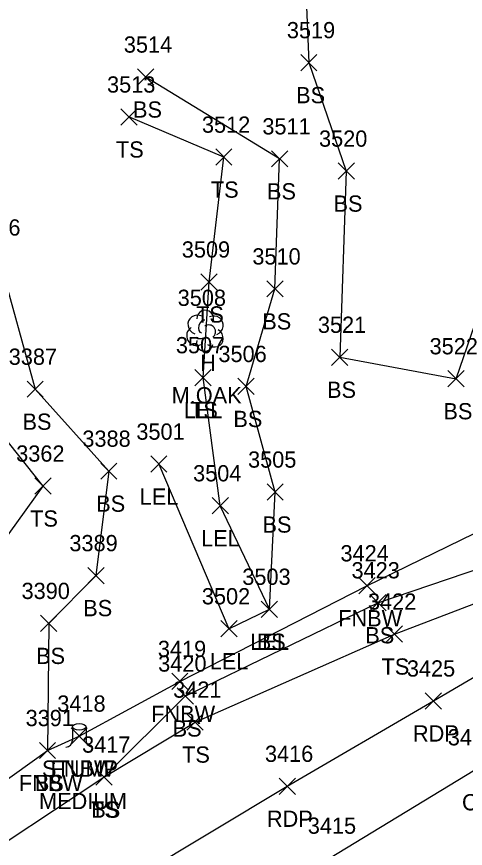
# Model space of a CAD drawing. Extents: x 1443590 to 1445966, y 578314 to 580556.
# Drawn here: x 1444037.5 to 1444092.8, y 578862 to 578964.4 of the extents above; entities that cross this region are included whole.
import ezdxf

# ---------------------------------------------------------------- set-up
doc = ezdxf.new("R2010")
doc.units = 0
for name, color, linetype in [('L_A', 7, 'Continuous'), ('L_C', 7, 'Continuous'), ('L_I', 7, 'Continuous'), ('L_TIC', 7, 'Continuous'), ('LARO', 7, 'Continuous'), ('LELB', 7, 'Continuous'), ('LFNC', 7, 'Continuous'), ('LTD', 7, 'Continuous'), ('LTS', 7, 'Continuous'), ('P_A', 7, 'Continuous'), ('P_I', 7, 'Continuous'), ('P_TIC', 7, 'Continuous'), ('PET', 7, 'Continuous'), ('PRC', 7, 'Continuous')]:
    doc.layers.add(name, color=color, linetype=linetype)

msp = doc.modelspace()

# ---------------------------------------------------------------- linework, layer by layer
at = {"layer": 'L_TIC'}
for points in [[(1444072.48, 578957.72), (1444074.48, 578959.72)], [(1444074.48, 578957.72), (1444072.48, 578959.72)], [(1444052.39, 578955.95), (1444054.39, 578957.95)], [(1444054.39, 578955.95), (1444052.39, 578957.95)], [(1444050.32, 578951.03), (1444052.32, 578953.03)], [(1444052.32, 578951.03), (1444050.32, 578953.03)], [(1444062.01, 578946.09), (1444064.01, 578948.09)], [(1444064.01, 578946.09), (1444062.01, 578948.09)], [(1444068.89, 578945.88), (1444070.89, 578947.88)], [(1444070.89, 578945.88), (1444068.89, 578947.88)], [(1444077.09, 578944.37), (1444079.09, 578946.37)], [(1444079.09, 578944.37), (1444077.09, 578946.37)], [(1444060.19, 578930.72), (1444062.19, 578932.72)], [(1444062.19, 578930.72), (1444060.19, 578932.72)], [(1444068.31, 578929.87), (1444070.31, 578931.87)], [(1444070.31, 578929.87), (1444068.31, 578931.87)], [(1444076.29, 578921.45), (1444078.29, 578923.45)], [(1444078.29, 578921.45), (1444076.29, 578923.45)], [(1444059.45, 578918.94), (1444061.45, 578920.94)], [(1444061.45, 578918.94), (1444059.45, 578920.94)], [(1444059.45, 578918.94), (1444061.45, 578920.94)], [(1444061.45, 578918.94), (1444059.45, 578920.94)], [(1444090.62, 578918.81), (1444092.62, 578920.81)], [(1444092.62, 578918.81), (1444090.62, 578920.81)], [(1444038.78, 578917.52), (1444040.78, 578919.52)], [(1444040.78, 578917.52), (1444038.78, 578919.52)], [(1444064.75, 578917.86), (1444066.75, 578919.86)], [(1444066.75, 578917.86), (1444064.75, 578919.86)], [(1444054.01, 578908.3), (1444056.01, 578910.3)], [(1444056.01, 578908.3), (1444054.01, 578910.3)], [(1444047.85, 578907.43), (1444049.85, 578909.43)], [(1444049.85, 578907.43), (1444047.85, 578909.43)], [(1444039.75, 578905.6), (1444041.75, 578907.6)], [(1444041.75, 578905.6), (1444039.75, 578907.6)], [(1444068.34, 578904.86), (1444070.34, 578906.86)], [(1444070.34, 578904.86), (1444068.34, 578906.86)], [(1444061.57, 578903.17), (1444063.57, 578905.17)], [(1444063.57, 578903.17), (1444061.57, 578905.17)], [(1444046.26, 578894.57), (1444048.26, 578896.57)], [(1444048.26, 578894.57), (1444046.26, 578896.57)], [(1444079.64, 578893.32), (1444081.64, 578895.32)], [(1444081.64, 578893.32), (1444079.64, 578895.32)], [(1444067.63, 578890.43), (1444069.63, 578892.43)], [(1444069.63, 578890.43), (1444067.63, 578892.43)], [(1444067.63, 578890.43), (1444069.63, 578892.43)], [(1444069.63, 578890.43), (1444067.63, 578892.43)], [(1444081, 578891.23), (1444083, 578893.23)], [(1444083, 578891.23), (1444081, 578893.23)], [(1444040.45, 578888.69), (1444042.45, 578890.69)], [(1444042.45, 578888.69), (1444040.45, 578890.69)], [(1444062.65, 578888.03), (1444064.65, 578890.03)], [(1444064.65, 578888.03), (1444062.65, 578890.03)], [(1444083.03, 578887.38), (1444085.03, 578889.38)], [(1444085.03, 578887.38), (1444083.03, 578889.38)], [(1444056.59, 578881.55), (1444058.59, 578883.55)], [(1444058.59, 578881.55), (1444056.59, 578883.55)], [(1444057.27, 578879.75), (1444059.27, 578881.75)], [(1444059.27, 578879.75), (1444057.27, 578881.75)], [(1444058.47, 578876.54), (1444060.47, 578878.54)], [(1444060.47, 578876.54), (1444058.47, 578878.54)], [(1444044.2, 578874.82), (1444046.2, 578876.82)], [(1444046.2, 578874.82), (1444044.2, 578876.82)], [(1444040.29, 578873.04), (1444042.29, 578875.04)], [(1444042.29, 578873.04), (1444040.29, 578875.04)], [(1444040.29, 578873.04), (1444042.29, 578875.04)], [(1444042.29, 578873.04), (1444040.29, 578875.04)], [(1444047.25, 578869.77), (1444049.25, 578871.77)], [(1444049.25, 578869.77), (1444047.25, 578871.77)], [(1444047.25, 578869.77), (1444049.25, 578871.77)], [(1444049.25, 578869.77), (1444047.25, 578871.77)]]:
    msp.add_lwpolyline(points, dxfattribs=at)
at = {"layer": 'LARO'}
msp.add_lwpolyline([(1444055.01, 578909.3), (1444063.65, 578889.03), (1444068.63, 578891.43), (1444062.57, 578904.17), (1444060.45, 578919.94)], dxfattribs=at)
at = {"layer": 'LELB'}
for points in [[(1444074.35, 578985.46), (1444072.77, 578975.47), (1444073.48, 578958.72), (1444078.09, 578945.37), (1444077.29, 578922.45), (1444091.62, 578919.81), (1444097.15, 578935.8), (1444104.08, 578947.68), (1444105.57, 578937.31), (1444105.86, 578926.31), (1444105.38, 578914.86)], [(1444028.79, 578962.23), (1444032.88, 578944.64), (1444035.34, 578934.43), (1444039.78, 578918.52), (1444048.85, 578908.43), (1444047.26, 578895.57), (1444041.45, 578889.69), (1444041.29, 578874.04)], [(1444068.63, 578891.43), (1444069.34, 578905.86), (1444065.75, 578918.86), (1444069.31, 578930.87), (1444069.89, 578946.88), (1444053.39, 578956.95)], [(1444060.45, 578919.94), (1444061.19, 578931.72), (1444063.01, 578947.09), (1444051.32, 578952.03)], [(1443938.52, 578791.48), (1443973.38, 578813.08), (1444005.23, 578834.2), (1444017.59, 578843.33), (1444019.71, 578848.08), (1444030.07, 578858.77), (1444048.25, 578870.77), (1444059.47, 578877.54), (1444084.03, 578888.38), (1444116.13, 578900.62), (1444133.65, 578911.54), (1444146.41, 578917.11), (1444149.51, 578920.45), (1444149.93, 578925.58), (1444153.52, 578930.88), (1444162.25, 578930.68), (1444174.13, 578936.01), (1444189.83, 578945.52), (1444198.3, 578950.86), (1444200.25, 578947.99), (1444203.06, 578948.48)], [(1444048.25, 578870.77), (1444058.27, 578880.75), (1444082, 578892.23), (1444114.39, 578903.2), (1444136.37, 578917.27), (1444137.43, 578920.19)], [(1443992.86, 578883.14), (1444004.82, 578882.17), (1444018.2, 578885.69), (1444031.18, 578893.34), (1444040.75, 578906.6), (1444034.4, 578914.56)]]:
    msp.add_lwpolyline(points, dxfattribs=at)
at = {"layer": 'LFNC'}
msp.add_lwpolyline([(1444008.03, 578853.09), (1444019.51, 578860.12), (1444026.6, 578863.53), (1444041.29, 578874.04), (1444045.2, 578875.82), (1444057.59, 578882.55), (1444080.64, 578894.32), (1444110.52, 578908.89), (1444116.81, 578913.3)], dxfattribs=at)
at = {"layer": 'LTD'}
msp.add_line((1444060.67, 578925.77), (1444060.67, 578925.77), dxfattribs=at)
msp.add_line((1444060.67, 578925.77), (1444060.67, 578925.77), dxfattribs=at)
msp.add_arc((1444060.72, 578927.2), 1.05, 335.5272, 180.9563, dxfattribs=at)
for centre, major_axis, ratio, start_param, end_param in [((1444059.88, 578926.43), (1.21, -0.51), 0.895232, 1.570796, 4.712389), ((1444061.71, 578926.35), (-1.14, -0.48), 0.949671, 1.570796, 4.712389), ((1444060.46, 578926.23), (-0.208, -0.792), 0.645439, 3.141593, 6.283185), ((1444061.17, 578925.6), (-0.5, 0.667), 0.989748, 3.141593, 6.283185), ((1444059.59, 578925.06), (0.58, -1.04), 0.959034, 3.141593, 6.283185), ((1444061.67, 578924.93), (-1.09, 0.79), 0.841452, 1.570796, 4.712389), ((1444060.67, 578924.27), (0.26, 1.06), 0.942809, 1.570796, 4.712389), ((1444060.21, 578925.02), (-0.625, -0.083), 0.423636, 0, 3.141593)]:
    msp.add_ellipse(centre, major_axis=major_axis, ratio=ratio, start_param=start_param, end_param=end_param, dxfattribs=at)
at = {"layer": 'LTS'}
for p, q in [((1444044.37, 578876.96), (1444044.37, 578875.29)), ((1444046.04, 578876.79), (1444046.04, 578876.96)), ((1444046.04, 578876.96), (1444046.04, 578875.29)), ((1444045.2, 578875.81), (1444045.2, 578875.81)), ((1444045.2, 578875.81), (1444045.2, 578875.81)), ((1444045.2, 578875.79), (1444045.2, 578875.79))]:
    msp.add_line(p, q, dxfattribs=at)
msp.add_circle((1444045.2, 578875.81), 0.0833, dxfattribs=at)
for centre, start, end in [((1444043.54, 578875.29), 270, 360), ((1444046.87, 578875.29), 180, 270)]:
    msp.add_arc(centre, 0.833, start, end, dxfattribs=at)
msp.add_ellipse((1444045.2, 578876.96), major_axis=(-0.833, 0), ratio=0.5, dxfattribs=at)
at = {"layer": 'P_TIC'}
for points in [[(1444087.82, 578879.14), (1444089.82, 578881.14)], [(1444089.82, 578879.14), (1444087.82, 578881.14)], [(1444069.83, 578868.64), (1444071.83, 578870.64)], [(1444071.83, 578868.64), (1444069.83, 578870.64)]]:
    msp.add_lwpolyline(points, dxfattribs=at)
at = {"layer": 'PET'}
msp.add_lwpolyline([(1443601.36, 578573.38), (1443632.23, 578593.39), (1443639.99, 578598.09), (1443685.58, 578628.02), (1443724.74, 578653.09), (1443761.98, 578676.74), (1443793.7, 578697.2), (1443832.46, 578722.27), (1443867.74, 578744.22), (1443903.66, 578767.03), (1443939.74, 578789.58), (1443974.31, 578811.25), (1444005.54, 578830.37), (1444024.78, 578842.02), (1444070.83, 578869.64), (1444088.82, 578880.14), (1444118.02, 578897.28), (1444147.48, 578914.76), (1444176.13, 578931.32), (1444203.82, 578947.29), (1444208.88, 578939.04), (1444214.07, 578930.35)], dxfattribs=at)
at = {"layer": 'PRC'}
msp.add_lwpolyline([(1443607.19, 578563.71), (1443645.74, 578588.68), (1443691.8, 578618.64), (1443730.92, 578643.94), (1443766.58, 578667.23), (1443799.08, 578688.06), (1443838.06, 578712.83), (1443872.72, 578734.91), (1443908.54, 578757.41), (1443944.72, 578780.26), (1443979.55, 578801.84), (1444011.31, 578821.61), (1444031.47, 578833.87), (1444076.05, 578860.79), (1444093.92, 578871.67), (1444123.23, 578888.92), (1444152.19, 578905.95), (1444180.96, 578922.73), (1444208.88, 578939.04)], dxfattribs=at)

# ---------------------------------------------------------------- texts
at = {"layer": 'L_A'}
for s, p in [('BS', (1444071.92, 578953.72)), ('BS', (1444051.83, 578951.95)), ('TS', (1444049.73, 578947.03)), ('TS', (1444061.42, 578942.09)), ('BS', (1444068.33, 578941.88)), ('BS', (1444076.53, 578940.37)), ('TS', (1444059.6, 578926.72)), ('BS', (1444067.75, 578925.87)), ('H', (1444060.1, 578920.77)), ('BS', (1444075.73, 578917.45)), ('LEL', (1444058.08, 578914.94)), ('TS', (1444058.86, 578914.94)), ('BS', (1444090.06, 578914.81)), ('BS', (1444038.22, 578913.52)), ('BS', (1444064.19, 578913.86)), ('LEL', (1444052.65, 578904.3)), ('BS', (1444047.3, 578903.43)), ('TS', (1444039.16, 578901.6)), ('BS', (1444067.78, 578900.86)), ('LEL', (1444060.21, 578899.17)), ('BS', (1444045.7, 578890.57)), ('FNBW', (1444077.11, 578889.32)), ('LEL', (1444066.27, 578886.43)), ('BS', (1444067.07, 578886.43)), ('BS', (1444080.44, 578887.23)), ('BS', (1444039.89, 578884.69)), ('LEL', (1444061.28, 578884.03)), ('TS', (1444082.44, 578883.38)), ('FNBW', (1444054.07, 578877.55)), ('BS', (1444056.71, 578875.75)), ('TS', (1444057.88, 578872.54)), ('STUMP', (1444040.62, 578870.82)), ('FNBW', (1444041.67, 578870.82)), ('FNBW', (1444037.77, 578869.04)), ('BS', (1444039.74, 578869.04)), ('TS', (1444046.66, 578865.77)), ('BS', (1444046.69, 578865.77))]:
    msp.add_text(s, height=2, dxfattribs=at).set_placement(p)
at = {"layer": 'L_C'}
for s, p in [('M.OAK', (1444056.59, 578916.77)), ('MEDIUM', (1444040.25, 578866.82))]:
    msp.add_text(s, height=2, dxfattribs=at).set_placement(p)
at = {"layer": 'L_I'}
for s, p in [('3519', (1444070.78, 578961.72)), ('3514', (1444050.7, 578959.95)), ('3513', (1444048.63, 578955.03)), ('3512', (1444060.32, 578950.09)), ('3511', (1444067.76, 578949.88)), ('3520', (1444074.74, 578948.37)), ('3386', (1444032.02, 578937.43)), ('3509', (1444057.84, 578934.72)), ('3510', (1444066.53, 578933.87)), ('3508', (1444057.33, 578928.77)), ('3521', (1444074.6, 578925.45)), ('3507', (1444057.11, 578922.94)), ('3507', (1444057.11, 578922.94)), ('3522', (1444088.36, 578922.81)), ('3387', (1444036.52, 578921.52)), ('3506', (1444062.35, 578921.86)), ('3501', (1444052.24, 578912.3)), ('3388', (1444045.59, 578911.43)), ('3362', (1444037.44, 578909.6)), ('3505', (1444066, 578908.86)), ('3504', (1444059.23, 578907.17)), ('3389', (1444043.99, 578898.57)), ('3424', (1444077.38, 578897.32)), ('3423', (1444078.74, 578895.23)), ('3503', (1444065.29, 578894.43)), ('3503', (1444065.29, 578894.43)), ('3390', (1444038.1, 578892.69)), ('3502', (1444060.31, 578892.03)), ('3422', (1444080.77, 578891.38)), ('3419', (1444054.89, 578885.55)), ('3420', (1444054.93, 578883.75)), ('3421', (1444056.78, 578880.54)), ('3418', (1444042.5, 578878.82)), ('3418', (1444042.5, 578878.82)), ('3391', (1444038.6, 578877.04)), ('3391', (1444038.6, 578877.04)), ('3417', (1444045.56, 578873.77)), ('3417', (1444045.56, 578873.77))]:
    msp.add_text(s, height=2, dxfattribs=at).set_placement(p)
at = {"layer": 'P_A'}
for s, p in [('RDP', (1444086.31, 578875.14)), ('CR', (1444092.35, 578866.67)), ('RDP', (1444068.32, 578864.64))]:
    msp.add_text(s, height=2, dxfattribs=at).set_placement(p)
at = {"layer": 'P_I'}
for s, p in [('3425', (1444085.56, 578883.14)), ('3426', (1444090.6, 578874.67)), ('3416', (1444068.08, 578872.64)), ('3415', (1444073.36, 578863.79))]:
    msp.add_text(s, height=2, dxfattribs=at).set_placement(p)

doc.saveas('drawing.dxf')
